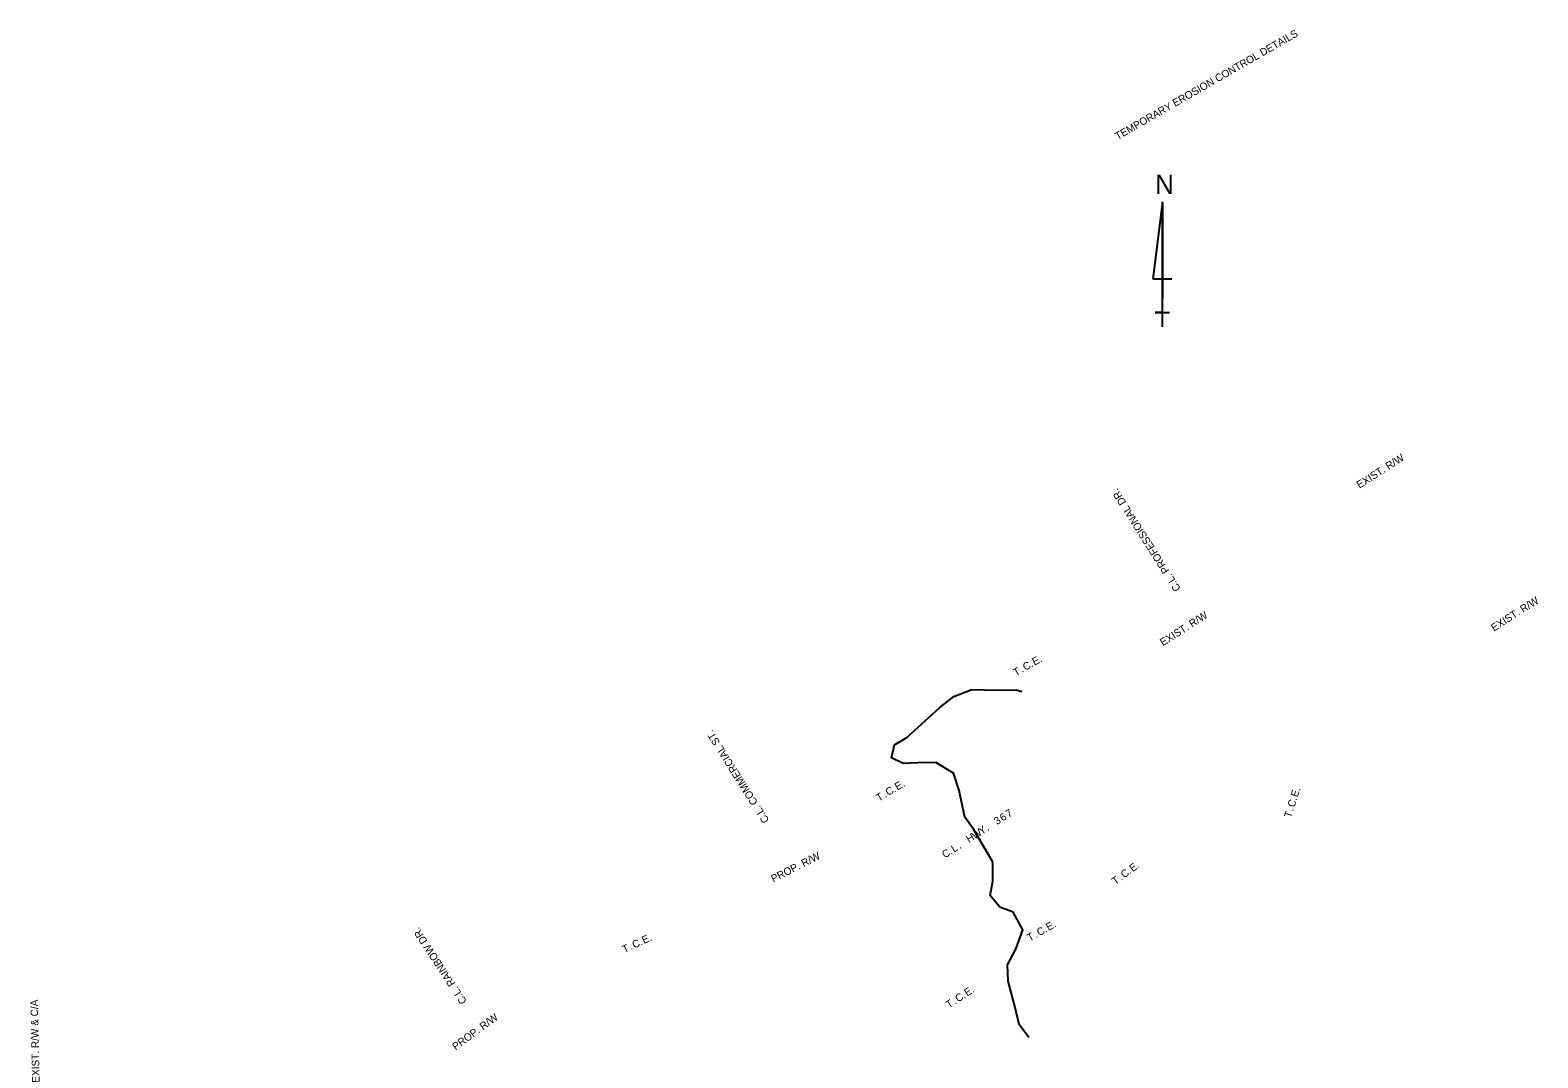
# Model space of a CAD drawing. Extents: x 1293866 to 1295382, y 223015 to 224618.
# Drawn here: x 1293894 to 1295100, y 223796 to 224618 of the extents above; entities that cross this region are included whole.
import ezdxf

# ---------------------------------------------------------------- set-up
doc = ezdxf.new("R2010")
doc.units = 0
for name, color, linetype in [('10Tan10', 7, 'Continuous'), ('Default', 7, 'Continuous'), ('Level 1', 7, 'Continuous'), ('R_Draft', 7, 'Continuous'), ('S_TREE', 7, 'Continuous')]:
    doc.layers.add(name, color=color, linetype=linetype)

msp = doc.modelspace()

# ---------------------------------------------------------------- linework, layer by layer
at = {"layer": 'Level 1'}
for p, q in [((1294799.9, 224480.6), (1294792.2, 224419.1)), ((1294799.9, 224380.6), (1294799.9, 224480.6)), ((1294799.9, 224480.6), (1294799.9, 224403.7)), ((1294792.2, 224419.1), (1294807.5, 224419.1)), ((1294799.9, 224380.6), (1294799.9, 224403.7)), ((1294799.9, 224392.1), (1294794.1, 224392.1)), ((1294794.1, 224392.1), (1294805.6, 224392.1)), ((1294799.9, 224380.6), (1294799.9, 224392.1))]:
    msp.add_line(p, q, dxfattribs=at)
at = {"layer": 'S_TREE'}
msp.add_lwpolyline([(1294693.2, 223812.3), (1294685.3, 223822.8), (1294682.3, 223836.4), (1294676.7, 223857.3), (1294676, 223870.5), (1294682.6, 223882.9), (1294688.4, 223898.4), (1294680.7, 223912.7), (1294670, 223916.6), (1294662.1, 223926), (1294664.4, 223937.4), (1294664.2, 223952.7), (1294658.8, 223962.3), (1294648.8, 223979.1), (1294641.9, 223988.5), (1294637.4, 224009.8), (1294632.9, 224023.7), (1294618.8, 224032.3), (1294604.2, 224031.9), (1294592.5, 224031.4), (1294583.2, 224035.9), (1294585.8, 224046.5), (1294595.6, 224052.4), (1294621.9, 224076.4), (1294633.2, 224085), (1294647.6, 224090.6), (1294667.8, 224090.2), (1294683.1, 224090.4), (1294687.6, 224089)], dxfattribs=at)

# ---------------------------------------------------------------- texts
at = {"layer": '10Tan10'}
for s, rotation, p in [('EXIST. R/W', 32.6554, (1294957.6, 224251.2)), ('EXIST. R/W', 32.6554, (1295065.2, 224136.9)), ('EXIST. R/W', 32.6554, (1294800.4, 224125.2)), ('PROP. R/W', 27.1484, (1294488.8, 223936.2)), ('EXIST. R/W & C/A', 91.1935, (1293901.9, 223776.3)), ('PROP. R/W', 36.3386, (1294234.7, 223801.9))]:
    msp.add_text(s, height=6, rotation=rotation, dxfattribs=at).set_placement(p)
at = {"layer": 'Default'}
for s, rotation, p in [('C.L. PROFESSIONAL DR.', 122.35, (1294814.9, 224171.4)), ('C.L. COMMERCIAL ST.', 122.25, (1294485.7, 223986.1)), ('3', 32.6116, (1294667.6, 223982.1)), ('6', 32.6116, (1294672.2, 223985)), ('7', 32.6116, (1294677, 223988)), ('H', 32.6116, (1294645.3, 223967.8)), ('W', 32.6116, (1294649.8, 223970.7)), ('Y', 32.6116, (1294655.3, 223974.2)), ('.', 32.6116, (1294660.1, 223977.3)), ('L', 32.6116, (1294633.3, 223960.1)), ('.', 32.6116, (1294637.8, 223963)), ('C', 32.6116, (1294626, 223955.5)), ('.', 32.6116, (1294630.8, 223958.5)), ('C.L. RAINBOW DR.', 123.2, (1294243.9, 223841.4))]:
    msp.add_text(s, height=6, rotation=rotation, dxfattribs=at).set_placement(p)
at = {"layer": 'Level 1'}
msp.add_text('N', height=15.4, rotation=360, dxfattribs=at).set_placement((1294794.2, 224487))
at = {"layer": 'R_Draft'}
for s, rotation, p in [('TEMPORARY EROSION CONTROL DETAILS', 30, (1294764.2, 224530)), ('T', 29.4274, (1294682.7, 224101.1)), ('C', 29.4274, (1294690.3, 224105.5)), ('E', 29.4274, (1294697.8, 224109.7)), ('.', 29.4274, (1294695.2, 224108.2)), ('.', 29.4274, (1294702.5, 224112.3)), ('.', 29.4274, (1294687.8, 224104)), ('C', 30.9348, (1294580.7, 224005.4)), ('E', 30.9348, (1294588.1, 224009.8)), ('.', 30.9348, (1294592.7, 224012.6)), ('T', 30.9348, (1294573.2, 224000.9)), ('.', 30.9348, (1294578.2, 224003.9)), ('.', 30.9348, (1294585.6, 224008.3)), ('C', 72.0741, (1294905.5, 223996)), ('E', 72.0741, (1294908.1, 224004.2)), ('.', 72.0741, (1294907.2, 224001.4)), ('.', 72.0741, (1294909.8, 224009.3)), ('T', 72.0741, (1294902.8, 223987.6)), ('.', 72.0741, (1294904.6, 223993.2)), ('E', 36.3386, (1294776.2, 223944.5)), ('T', 36.3386, (1294762.2, 223934.2)), ('.', 36.3386, (1294766.9, 223937.7)), ('C', 36.3386, (1294769.3, 223939.5)), ('.', 36.3386, (1294773.8, 223942.8)), ('.', 36.3386, (1294780.5, 223947.7)), ('E', 29.4274, (1294708.9, 223897.5)), ('C', 25.0287, (1294377.5, 223883.4)), ('E', 25.0287, (1294385.3, 223887.1)), ('.', 25.0287, (1294390.2, 223889.3)), ('T', 29.4274, (1294693.8, 223889)), ('.', 29.4274, (1294698.9, 223891.8)), ('C', 29.4274, (1294701.5, 223893.3)), ('.', 29.4274, (1294706.4, 223896.1)), ('.', 29.4274, (1294713.6, 223900.2)), ('T', 25.0287, (1294369.6, 223879.7)), ('.', 25.0287, (1294374.9, 223882.2)), ('.', 25.0287, (1294382.7, 223885.8)), ('T', 33.1588, (1294629.2, 223835.5)), ('C', 33.1588, (1294636.6, 223840.3)), ('E', 33.1588, (1294643.8, 223845)), ('.', 33.1588, (1294641.3, 223843.4)), ('.', 33.1588, (1294648.3, 223847.9)), ('.', 33.1588, (1294634.1, 223838.7))]:
    msp.add_text(s, height=6, rotation=rotation, dxfattribs=at).set_placement(p)

doc.saveas('drawing.dxf')
